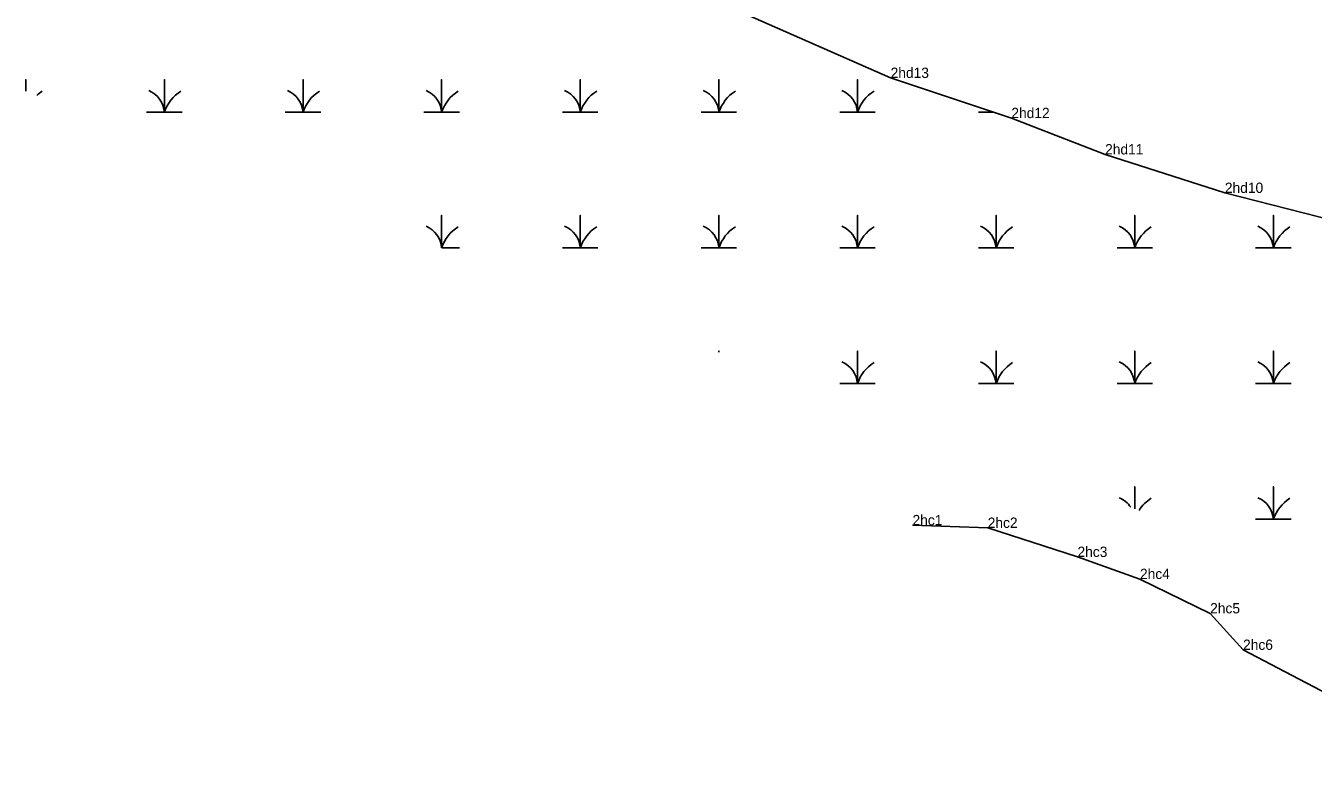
# Model space of a CAD drawing. Extents: x 2072529 to 2268796, y 436423 to 470406.
# Drawn here: x 2106175 to 2106799, y 453813 to 454182 of the extents above; entities that cross this region are included whole.
import ezdxf

# ---------------------------------------------------------------- set-up
doc = ezdxf.new("R2010")
doc.units = 0
for name, color, linetype in [('Exist Environmental Wetland Boundary', 7, 'Continuous'), ('Exist Environmental Wetland Boundary Cogo Comment', 7, 'Continuous'), ('Exist Hydro Swamp or Marsh', 7, 'Continuous'), ('Old_Level_20', 7, 'Continuous')]:
    doc.layers.add(name, color=color, linetype=linetype)

msp = doc.modelspace()

# ---------------------------------------------------------------- linework, layer by layer
at = {"layer": 'Exist Environmental Wetland Boundary'}
for points in [[(2106225.82, 454287.77), (2106335.08, 454245.31), (2106388.83, 454223.88), (2106440.81, 454219.04), (2106510.17, 454194.07), (2106594.46, 454156.94), (2106653.02, 454137.45), (2106698.5, 454119.85), (2106756.6, 454101.18), (2106817.34, 454085.64), (2106852.39, 454068.44), (2106873.69, 454065.6), (2106917.57, 454044.06), (2106999.1, 454017.23), (2107048.91, 454001.25), (2107052.03, 453978.75), (2107063.45, 453958.83), (2107056.1, 453930.45)], [(2107175.9, 453920.17), (2107141.9, 453928.29), (2107104.26, 453928.26), (2107094.68, 453905.35), (2107083.05, 453891.68), (2107056.7, 453883.25), (2107040.21, 453845.27), (2106990.6, 453814.72), (2106937.33, 453813.49), (2106882.67, 453831.84), (2106873.68, 453824.36), (2106826.94, 453847.47), (2106765.43, 453879.6), (2106749.46, 453897.3), (2106715.42, 453913.96), (2106685.12, 453924.67), (2106641.55, 453938.77), (2106605.07, 453940.05)]]:
    msp.add_lwpolyline(points, dxfattribs=at)
at = {"layer": 'Exist Hydro Swamp or Marsh'}
for points in [[(2106174.89, 454150.51), (2106174.89, 454156.11), (2106174.89, 454150.51)], [(2106233.53, 454140.33), (2106242.14, 454140.33), (2106242.14, 454156.11), (2106242.14, 454140.33), (2106250.74, 454140.33)], [(2106300.78, 454140.33), (2106309.39, 454140.33), (2106309.39, 454156.11), (2106309.39, 454140.33), (2106317.99, 454140.33)], [(2106368.03, 454140.33), (2106376.64, 454140.33), (2106376.64, 454156.11), (2106376.64, 454140.33), (2106385.24, 454140.33)], [(2106435.28, 454140.33), (2106443.89, 454140.33), (2106443.89, 454156.11), (2106443.89, 454140.33), (2106452.49, 454140.33)], [(2106502.53, 454140.33), (2106511.14, 454140.33), (2106511.14, 454156.11), (2106511.14, 454140.33), (2106519.74, 454140.33)], [(2106569.78, 454140.33), (2106578.39, 454140.33), (2106578.39, 454156.11), (2106578.39, 454140.33), (2106586.99, 454140.33)], [(2106637.03, 454140.33), (2106644.39, 454140.33)], [(2106376.64, 454074.58), (2106376.64, 454090.31), (2106376.64, 454074.58)], [(2106435.28, 454074.53), (2106443.89, 454074.53), (2106443.89, 454090.31), (2106443.89, 454074.53), (2106452.49, 454074.53)], [(2106502.53, 454074.53), (2106511.14, 454074.53), (2106511.14, 454090.31), (2106511.14, 454074.53), (2106519.74, 454074.53)], [(2106569.78, 454074.53), (2106578.39, 454074.53), (2106578.39, 454090.31), (2106578.39, 454074.53), (2106586.99, 454074.53)], [(2106637.03, 454074.53), (2106645.64, 454074.53), (2106645.64, 454090.31), (2106645.64, 454074.53), (2106654.24, 454074.53)], [(2106704.28, 454074.53), (2106712.89, 454074.53), (2106712.89, 454090.31), (2106712.89, 454074.53), (2106721.49, 454074.53)], [(2106771.53, 454074.53), (2106780.14, 454074.53), (2106780.14, 454090.31), (2106780.14, 454074.53), (2106788.74, 454074.53)], [(2106376.78, 454074.53), (2106385.24, 454074.53)], [(2106511.14, 454023.96), (2106511.14, 454024.51), (2106511.14, 454023.96)], [(2106569.78, 454008.73), (2106578.39, 454008.73), (2106578.39, 454024.51), (2106578.39, 454008.73), (2106586.99, 454008.73)], [(2106637.03, 454008.73), (2106645.64, 454008.73), (2106645.64, 454024.51), (2106645.64, 454008.73), (2106654.24, 454008.73)], [(2106704.28, 454008.73), (2106712.89, 454008.73), (2106712.89, 454024.51), (2106712.89, 454008.73), (2106721.49, 454008.73)], [(2106771.53, 454008.73), (2106780.14, 454008.73), (2106780.14, 454024.51), (2106780.14, 454008.73), (2106788.74, 454008.73)], [(2106712.89, 453948.03), (2106712.89, 453958.71), (2106712.89, 453948.03)], [(2106771.53, 453942.93), (2106780.14, 453942.93), (2106780.14, 453958.71), (2106780.14, 453942.93), (2106788.74, 453942.93)]]:
    msp.add_lwpolyline(points, dxfattribs=at)
for centre, radius, start, end in [((2106193.13, 454134.26), 19.22, 122.12745, 132.19295), ((2106229.87, 454139.44), 12.3, 4.14034, 67.53497), ((2106260.38, 454134.26), 19.22, 122.12745, 161.62219), ((2106297.12, 454139.44), 12.3, 4.14034, 67.53497), ((2106327.63, 454134.26), 19.22, 122.12745, 161.62219), ((2106364.37, 454139.44), 12.3, 4.14034, 67.53497), ((2106394.88, 454134.26), 19.22, 122.12745, 161.62219), ((2106431.62, 454139.44), 12.3, 4.14034, 67.53497), ((2106462.13, 454134.26), 19.22, 122.12745, 161.62219), ((2106498.87, 454139.44), 12.3, 4.14034, 67.53497), ((2106529.38, 454134.26), 19.22, 122.12745, 161.62219), ((2106566.12, 454139.44), 12.3, 4.14034, 67.53497), ((2106596.63, 454134.26), 19.22, 122.12745, 161.62219), ((2106364.37, 454073.64), 12.3, 4.40505, 67.53497), ((2106431.62, 454073.64), 12.3, 4.14034, 67.53497), ((2106498.87, 454073.64), 12.3, 4.14034, 67.53497), ((2106566.12, 454073.64), 12.3, 4.14034, 67.53497), ((2106633.37, 454073.64), 12.3, 4.14034, 67.53497), ((2106700.62, 454073.64), 12.3, 4.14034, 67.53497), ((2106767.87, 454073.64), 12.3, 4.14034, 67.53497), ((2106394.88, 454068.46), 19.22, 122.12745, 161.46846), ((2106462.13, 454068.46), 19.22, 122.12745, 161.62219), ((2106529.38, 454068.46), 19.22, 122.12745, 161.62219), ((2106596.63, 454068.46), 19.22, 122.12745, 161.62219), ((2106663.88, 454068.46), 19.22, 122.12745, 161.62219), ((2106731.13, 454068.46), 19.22, 122.12745, 161.62219), ((2106798.38, 454068.46), 19.22, 122.12745, 161.62219), ((2106566.12, 454007.84), 12.3, 4.14034, 67.53497), ((2106596.63, 454002.66), 19.22, 122.12745, 161.62219), ((2106633.37, 454007.84), 12.3, 4.14034, 67.53497), ((2106663.88, 454002.66), 19.22, 122.12745, 161.62219), ((2106700.62, 454007.84), 12.3, 4.14034, 67.53497), ((2106731.13, 454002.66), 19.22, 122.12745, 161.62219), ((2106767.87, 454007.84), 12.3, 4.14034, 67.53497), ((2106798.38, 454002.66), 19.22, 122.12745, 161.62219), ((2106700.62, 453942.04), 12.3, 33.18148, 67.53497), ((2106731.13, 453936.86), 19.22, 122.12745, 147.30499), ((2106767.87, 453942.04), 12.3, 4.14034, 67.53497), ((2106798.38, 453936.86), 19.22, 122.12745, 161.62219)]:
    msp.add_arc(centre, radius, start, end, dxfattribs=at)
at = {"layer": 'Old_Level_20'}
for p, q in [((2106594.46, 454156.94), (2106594.46, 454156.94)), ((2106653.02, 454137.45), (2106653.02, 454137.45)), ((2106698.5, 454119.85), (2106698.5, 454119.85)), ((2106756.6, 454101.18), (2106756.6, 454101.18)), ((2106605.07, 453940.05), (2106605.07, 453940.05)), ((2106641.55, 453938.77), (2106641.55, 453938.77)), ((2106685.12, 453924.67), (2106685.12, 453924.67)), ((2106715.42, 453913.96), (2106715.42, 453913.96)), ((2106749.46, 453897.3), (2106749.46, 453897.3)), ((2106765.42, 453879.6), (2106765.42, 453879.6))]:
    msp.add_line(p, q, dxfattribs=at)

# ---------------------------------------------------------------- texts
at = {"layer": 'Exist Environmental Wetland Boundary Cogo Comment'}
for s, p in [('2hd13', (2106594.46, 454156.94)), ('2hd12', (2106653.02, 454137.45)), ('2hd11', (2106698.5, 454119.85)), ('2hd10', (2106756.6, 454101.18)), ('2hc1', (2106605.07, 453940.05)), ('2hc2', (2106641.55, 453938.77)), ('2hc3', (2106685.12, 453924.67)), ('2hc4', (2106715.42, 453913.96)), ('2hc5', (2106749.46, 453897.3)), ('2hc6', (2106765.43, 453879.6))]:
    msp.add_text(s, height=5, dxfattribs=at).set_placement(p)

doc.saveas('drawing.dxf')
